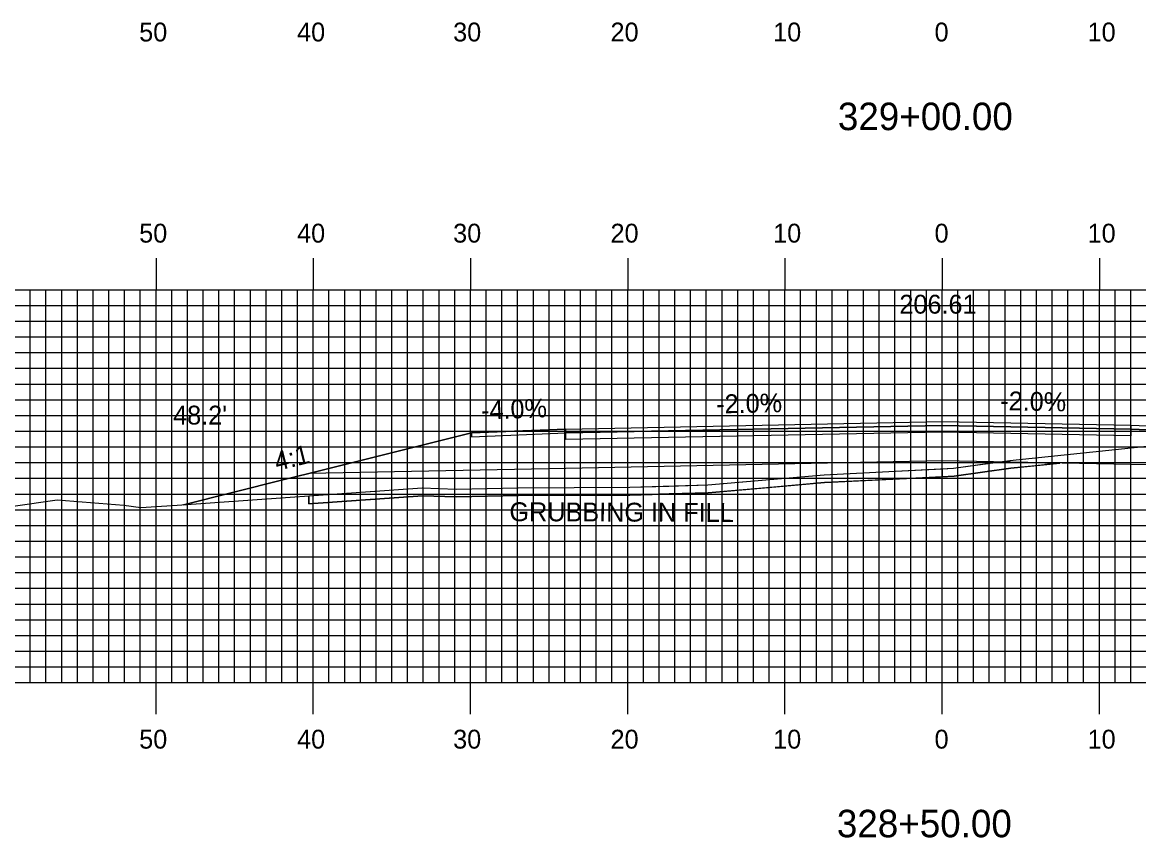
# Model space of a CAD drawing. Extents: x 1821998 to 1822342, y 442591 to 442811.
# Drawn here: x 1822105.8 to 1822176.8, y 442643.8 to 442695.7 of the extents above; entities that cross this region are included whole.
import ezdxf

# ---------------------------------------------------------------- set-up
doc = ezdxf.new("R2010")
doc.units = 0
for name, color, linetype in [('ANNOTATION', 7, 'Continuous'), ('D_Roadway_Centerline', 7, 'Continuous'), ('D_Roadway_Centerline_Text', 7, 'Continuous'), ('D_Roadway_Edge_Shoulder', 7, 'Continuous'), ('D_Roadway_Edge_TW', 7, 'Continuous'), ('D_Roadway_Pavement', 7, 'Continuous'), ('D_Roadway_SlopeLines', 7, 'Continuous'), ('D_Roadway_SubGrade', 7, 'Continuous'), ('D_Text_Standard', 7, 'Continuous'), ('GRUBBING IN FILL', 7, 'Continuous'), ('H_V ANNOTATION', 7, 'Continuous'), ('MAJOR', 7, 'Continuous'), ('MINOR', 7, 'Continuous'), ('S_Roadway_Centerline', 7, 'Continuous')]:
    doc.layers.add(name, color=color, linetype=linetype)

msp = doc.modelspace()

# ---------------------------------------------------------------- linework, layer by layer
at = {"layer": 'D_Roadway_Centerline'}
msp.add_lwpolyline([(1822116.014, 442664.985), (1822122.313, 442666.56), (1822123.967, 442666.973), (1822134.313, 442669.56), (1822140.325, 442669.8), (1822164.256, 442670.279), (1822176.256, 442670.039), (1822184.256, 442669.719), (1822194.43, 442667.175), (1822198.43, 442666.175), (1822212.608, 442669.72), (1822213.858, 442669.994), (1822215.108, 442670.192), (1822216.358, 442670.313), (1822217.608, 442670.357)], dxfattribs=at)
at = {"layer": 'D_Roadway_Edge_Shoulder'}
for points in [[(1822140.325, 442669.8), (1822134.313, 442669.56), (1822134.313, 442669.31), (1822140.325, 442669.55)], [(1822176.256, 442670.039), (1822184.256, 442669.719), (1822184.256, 442669.469), (1822176.256, 442669.789)]]:
    msp.add_lwpolyline(points, close=True, dxfattribs=at)
at = {"layer": 'D_Roadway_Edge_TW'}
msp.add_lwpolyline([(1822140.325, 442669.55), (1822140.325, 442669.8), (1822164.256, 442670.279), (1822176.256, 442670.039), (1822176.256, 442669.789), (1822164.256, 442670.029)], close=True, dxfattribs=at)
at = {"layer": 'D_Roadway_Pavement'}
msp.add_lwpolyline([(1822140.325, 442669.134), (1822140.325, 442669.55), (1822164.256, 442670.029), (1822176.256, 442669.789), (1822176.256, 442669.372), (1822164.256, 442669.612)], close=True, dxfattribs=at)
at = {"layer": 'D_Roadway_SlopeLines'}
msp.add_lwpolyline([(1822134.313, 442669.56), (1822123.967, 442666.973), (1822122.313, 442666.56), (1822116.014, 442664.985)], dxfattribs=at)
at = {"layer": 'D_Roadway_SubGrade'}
msp.add_lwpolyline([(1822140.325, 442667.3), (1822123.967, 442666.973), (1822134.313, 442669.56), (1822134.313, 442669.31), (1822140.325, 442669.55), (1822164.256, 442670.029), (1822176.256, 442669.789), (1822184.256, 442669.469), (1822184.256, 442669.719), (1822194.43, 442667.175), (1822176.256, 442667.539), (1822164.256, 442667.779)], close=True, dxfattribs=at)
at = {"layer": 'GRUBBING IN FILL'}
msp.add_line((1822123.967, 442665.545), (1822123.967, 442665.044), dxfattribs=at)
msp.add_line((1822123.967, 442665.545), (1822123.967, 442665.044), dxfattribs=at)
msp.add_lwpolyline([(1822123.967, 442665.044), (1822131.195, 442665.554), (1822133.353, 442665.482), (1822137.305, 442665.568), (1822144.394, 442665.597), (1822149.381, 442665.74), (1822156.779, 442666.39), (1822165.016, 442666.806), (1822168.616, 442667.303), (1822171.741, 442667.629)], dxfattribs=at)
msp.add_lwpolyline([(1822123.967, 442665.044), (1822131.195, 442665.554), (1822133.353, 442665.482), (1822137.305, 442665.568), (1822144.394, 442665.597), (1822149.381, 442665.74), (1822156.779, 442666.39), (1822165.016, 442666.806), (1822168.616, 442667.303), (1822171.741, 442667.629)], dxfattribs=at)
for points in [[(1822164.256, 442667.268), (1822164.969, 442667.304), (1822167.882, 442667.706), (1822171.741, 442667.629), (1822170.179, 442667.466), (1822168.616, 442667.303), (1822166.816, 442667.054), (1822165.016, 442666.806), (1822164.256, 442666.768)], [(1822164.256, 442667.268), (1822164.969, 442667.304), (1822167.882, 442667.706), (1822171.741, 442667.629), (1822170.179, 442667.466), (1822168.616, 442667.303), (1822166.816, 442667.054), (1822165.016, 442666.806), (1822164.256, 442666.768)], [(1822123.967, 442665.545), (1822131.186, 442666.054), (1822132.271, 442666.018), (1822133.356, 442665.982), (1822135.327, 442666.025), (1822137.298, 442666.068), (1822140.842, 442666.083), (1822144.386, 442666.097), (1822146.869, 442666.168), (1822149.352, 442666.24), (1822153.049, 442666.564), (1822156.745, 442666.889), (1822160.857, 442667.097), (1822164.256, 442667.268), (1822164.256, 442666.768), (1822160.898, 442666.598), (1822156.779, 442666.39), (1822153.08, 442666.065), (1822149.381, 442665.74), (1822146.888, 442665.669), (1822144.394, 442665.597), (1822140.849, 442665.583), (1822137.305, 442665.568), (1822135.329, 442665.525), (1822133.353, 442665.482), (1822131.195, 442665.554), (1822127.581, 442665.299), (1822123.967, 442665.044)], [(1822123.967, 442665.545), (1822131.186, 442666.054), (1822132.271, 442666.018), (1822133.356, 442665.982), (1822135.327, 442666.025), (1822137.298, 442666.068), (1822140.842, 442666.083), (1822144.386, 442666.097), (1822146.869, 442666.168), (1822149.352, 442666.24), (1822153.049, 442666.564), (1822156.745, 442666.889), (1822160.857, 442667.097), (1822164.256, 442667.268), (1822164.256, 442666.768), (1822160.898, 442666.598), (1822156.779, 442666.39), (1822153.08, 442666.065), (1822149.381, 442665.74), (1822146.888, 442665.669), (1822144.394, 442665.597), (1822140.849, 442665.583), (1822137.305, 442665.568), (1822135.329, 442665.525), (1822133.353, 442665.482), (1822131.195, 442665.554), (1822127.581, 442665.299), (1822123.967, 442665.044)]]:
    msp.add_lwpolyline(points, close=True, dxfattribs=at)
at = {"layer": 'MAJOR'}
for p, q in [((1822114.256, 442680.669), (1822114.256, 442678.665)), ((1822124.256, 442680.669), (1822124.256, 442678.665)), ((1822134.256, 442680.669), (1822134.256, 442678.665)), ((1822144.256, 442680.669), (1822144.256, 442678.665)), ((1822154.256, 442680.669), (1822154.256, 442678.665)), ((1822164.256, 442680.669), (1822164.256, 442678.665)), ((1822174.256, 442680.669), (1822174.256, 442678.665)), ((1822024.256, 442678.665), (1822304.256, 442678.665)), ((1822024.256, 442678.665), (1822304.256, 442678.665)), ((1822114.256, 442653.665), (1822114.256, 442678.665)), ((1822124.256, 442653.665), (1822124.256, 442678.665)), ((1822134.256, 442653.665), (1822134.256, 442678.665)), ((1822144.256, 442653.665), (1822144.256, 442678.665)), ((1822154.256, 442653.665), (1822154.256, 442678.665)), ((1822164.256, 442653.665), (1822164.256, 442678.665)), ((1822174.256, 442653.665), (1822174.256, 442678.665)), ((1822024.256, 442673.665), (1822304.256, 442673.665)), ((1822024.256, 442668.665), (1822304.256, 442668.665)), ((1822024.256, 442663.665), (1822304.256, 442663.665)), ((1822024.256, 442658.665), (1822304.256, 442658.665)), ((1822024.256, 442653.665), (1822304.256, 442653.665)), ((1822024.256, 442653.665), (1822304.256, 442653.665)), ((1822114.256, 442651.661), (1822114.256, 442653.665)), ((1822124.256, 442651.661), (1822124.256, 442653.665)), ((1822134.256, 442651.661), (1822134.256, 442653.665)), ((1822144.256, 442651.661), (1822144.256, 442653.665)), ((1822154.256, 442651.661), (1822154.256, 442653.665)), ((1822164.256, 442651.661), (1822164.256, 442653.665)), ((1822174.256, 442651.661), (1822174.256, 442653.665))]:
    msp.add_line(p, q, dxfattribs=at)
at = {"layer": 'MINOR'}
for p, q in [((1822106.256, 442653.665), (1822106.256, 442678.665)), ((1822107.256, 442653.665), (1822107.256, 442678.665)), ((1822108.256, 442653.665), (1822108.256, 442678.665)), ((1822109.256, 442653.665), (1822109.256, 442678.665)), ((1822110.256, 442653.665), (1822110.256, 442678.665)), ((1822111.256, 442653.665), (1822111.256, 442678.665)), ((1822112.256, 442653.665), (1822112.256, 442678.665)), ((1822113.256, 442653.665), (1822113.256, 442678.665)), ((1822115.256, 442653.665), (1822115.256, 442678.665)), ((1822116.256, 442653.665), (1822116.256, 442678.665)), ((1822117.256, 442653.665), (1822117.256, 442678.665)), ((1822118.256, 442653.665), (1822118.256, 442678.665)), ((1822119.256, 442653.665), (1822119.256, 442678.665)), ((1822120.256, 442653.665), (1822120.256, 442678.665)), ((1822121.256, 442653.665), (1822121.256, 442678.665)), ((1822122.256, 442653.665), (1822122.256, 442678.665)), ((1822123.256, 442653.665), (1822123.256, 442678.665)), ((1822125.256, 442653.665), (1822125.256, 442678.665)), ((1822126.256, 442653.665), (1822126.256, 442678.665)), ((1822127.256, 442653.665), (1822127.256, 442678.665)), ((1822128.256, 442653.665), (1822128.256, 442678.665)), ((1822129.256, 442653.665), (1822129.256, 442678.665)), ((1822130.256, 442653.665), (1822130.256, 442678.665)), ((1822131.256, 442653.665), (1822131.256, 442678.665)), ((1822132.256, 442653.665), (1822132.256, 442678.665)), ((1822133.256, 442653.665), (1822133.256, 442678.665)), ((1822135.256, 442653.665), (1822135.256, 442678.665)), ((1822136.256, 442653.665), (1822136.256, 442678.665)), ((1822137.256, 442653.665), (1822137.256, 442678.665)), ((1822138.256, 442653.665), (1822138.256, 442678.665)), ((1822139.256, 442653.665), (1822139.256, 442678.665)), ((1822140.256, 442653.665), (1822140.256, 442678.665)), ((1822141.256, 442653.665), (1822141.256, 442678.665)), ((1822142.256, 442653.665), (1822142.256, 442678.665)), ((1822143.256, 442653.665), (1822143.256, 442678.665)), ((1822145.256, 442653.665), (1822145.256, 442678.665)), ((1822146.256, 442653.665), (1822146.256, 442678.665)), ((1822147.256, 442653.665), (1822147.256, 442678.665)), ((1822148.256, 442653.665), (1822148.256, 442678.665)), ((1822149.256, 442653.665), (1822149.256, 442678.665)), ((1822150.256, 442653.665), (1822150.256, 442678.665)), ((1822151.256, 442653.665), (1822151.256, 442678.665)), ((1822152.256, 442653.665), (1822152.256, 442678.665)), ((1822153.256, 442653.665), (1822153.256, 442678.665)), ((1822155.256, 442653.665), (1822155.256, 442678.665)), ((1822156.256, 442653.665), (1822156.256, 442678.665)), ((1822157.256, 442653.665), (1822157.256, 442678.665)), ((1822158.256, 442653.665), (1822158.256, 442678.665)), ((1822159.256, 442653.665), (1822159.256, 442678.665)), ((1822160.256, 442653.665), (1822160.256, 442678.665)), ((1822161.256, 442653.665), (1822161.256, 442678.665)), ((1822162.256, 442653.665), (1822162.256, 442678.665)), ((1822163.256, 442653.665), (1822163.256, 442678.665)), ((1822165.256, 442653.665), (1822165.256, 442678.665)), ((1822166.256, 442653.665), (1822166.256, 442678.665)), ((1822167.256, 442653.665), (1822167.256, 442678.665)), ((1822168.256, 442653.665), (1822168.256, 442678.665)), ((1822169.256, 442653.665), (1822169.256, 442678.665)), ((1822170.256, 442653.665), (1822170.256, 442678.665)), ((1822171.256, 442653.665), (1822171.256, 442678.665)), ((1822172.256, 442653.665), (1822172.256, 442678.665)), ((1822173.256, 442653.665), (1822173.256, 442678.665)), ((1822175.256, 442653.665), (1822175.256, 442678.665)), ((1822176.256, 442653.665), (1822176.256, 442678.665)), ((1822024.256, 442677.665), (1822304.256, 442677.665)), ((1822024.256, 442676.665), (1822304.256, 442676.665)), ((1822024.256, 442675.665), (1822304.256, 442675.665)), ((1822024.256, 442674.665), (1822304.256, 442674.665)), ((1822024.256, 442672.665), (1822304.256, 442672.665)), ((1822024.256, 442671.665), (1822304.256, 442671.665)), ((1822024.256, 442670.665), (1822304.256, 442670.665)), ((1822024.256, 442669.665), (1822304.256, 442669.665)), ((1822024.256, 442667.665), (1822304.256, 442667.665)), ((1822024.256, 442666.665), (1822304.256, 442666.665)), ((1822024.256, 442665.665), (1822304.256, 442665.665)), ((1822024.256, 442664.665), (1822304.256, 442664.665)), ((1822024.256, 442662.665), (1822304.256, 442662.665)), ((1822024.256, 442661.665), (1822304.256, 442661.665)), ((1822024.256, 442660.665), (1822304.256, 442660.665)), ((1822024.256, 442659.665), (1822304.256, 442659.665)), ((1822024.256, 442657.665), (1822304.256, 442657.665)), ((1822024.256, 442656.665), (1822304.256, 442656.665)), ((1822024.256, 442655.665), (1822304.256, 442655.665)), ((1822024.256, 442654.665), (1822304.256, 442654.665))]:
    msp.add_line(p, q, dxfattribs=at)
at = {"layer": 'S_Roadway_Centerline'}
msp.add_lwpolyline([(1822094.403, 442663.338), (1822107.969, 442665.291), (1822112.205, 442664.954), (1822113.286, 442664.811), (1822115.598, 442664.956), (1822131.186, 442666.054), (1822133.356, 442665.982), (1822137.298, 442666.068), (1822144.386, 442666.097), (1822149.352, 442666.24), (1822156.745, 442666.889), (1822164.969, 442667.304), (1822168.556, 442667.799), (1822181.968, 442669.2), (1822182.922, 442669.274), (1822194.41, 442669.745), (1822195.717, 442669.795), (1822197.791, 442669.932), (1822200.027, 442670.013), (1822201.445, 442670.065), (1822211.179, 442670.346), (1822212.279, 442670.331), (1822217.357, 442670.356), (1822227.858, 442670.416)], dxfattribs=at)

# ---------------------------------------------------------------- texts
at = {"layer": 'ANNOTATION'}
for s, rotation, p in [('-2.0%', 1.14576, (1822149.897, 442670.792)), ('-2.0%', 358.85424, (1822167.942, 442671.006)), ('-4.0%', 2.29061, (1822134.951, 442670.387)), ('4:1', 14.03624, (1822121.953, 442667.124))]:
    msp.add_text(s, height=1.2, rotation=rotation, dxfattribs=at).set_placement(p)
at = {"layer": 'D_Roadway_Centerline'}
for s, p in [('C', (1822164.251, 442670.279)), ('L', (1822164.256, 442670.272))]:
    msp.add_text(s, height=0.0146, dxfattribs=at).set_placement(p)
at = {"layer": 'D_Roadway_Centerline_Text'}
msp.add_text('206.61', height=1.2, dxfattribs=at).set_placement((1822161.538, 442677.145))
at = {"layer": 'D_Text_Standard'}
msp.add_text("48.2'", height=1.2, dxfattribs=at).set_placement((1822115.342, 442670.087))
at = {"layer": 'GRUBBING IN FILL'}
msp.add_text('GRUBBING IN FILL', height=1.2, rotation=359.80532, dxfattribs=at).set_placement((1822136.733, 442663.938))
at = {"layer": 'H_V ANNOTATION'}
for s, height, p in [('50', 1.2, (1822113.186, 442694.465)), ('40', 1.2, (1822123.229, 442694.465)), ('30', 1.2, (1822133.154, 442694.465)), ('20', 1.2, (1822143.164, 442694.465)), ('10', 1.2, (1822153.507, 442694.465)), ('0', 1.2, (1822163.774, 442694.465)), ('10', 1.2, (1822173.507, 442694.465)), ('329+00.00', 1.75, (1822157.624, 442688.821)), ('50', 1.2, (1822113.186, 442681.665)), ('40', 1.2, (1822123.229, 442681.665)), ('30', 1.2, (1822133.154, 442681.665)), ('20', 1.2, (1822143.164, 442681.665)), ('10', 1.2, (1822153.507, 442681.665)), ('0', 1.2, (1822163.774, 442681.665)), ('10', 1.2, (1822173.507, 442681.665)), ('50', 1.2, (1822113.186, 442649.465)), ('40', 1.2, (1822123.229, 442649.465)), ('30', 1.2, (1822133.154, 442649.465)), ('20', 1.2, (1822143.164, 442649.465)), ('10', 1.2, (1822153.507, 442649.465)), ('0', 1.2, (1822163.774, 442649.465)), ('10', 1.2, (1822173.507, 442649.465)), ('328+50.00', 1.75, (1822157.561, 442643.821))]:
    msp.add_text(s, height=height, dxfattribs=at).set_placement(p)

doc.saveas('drawing.dxf')
